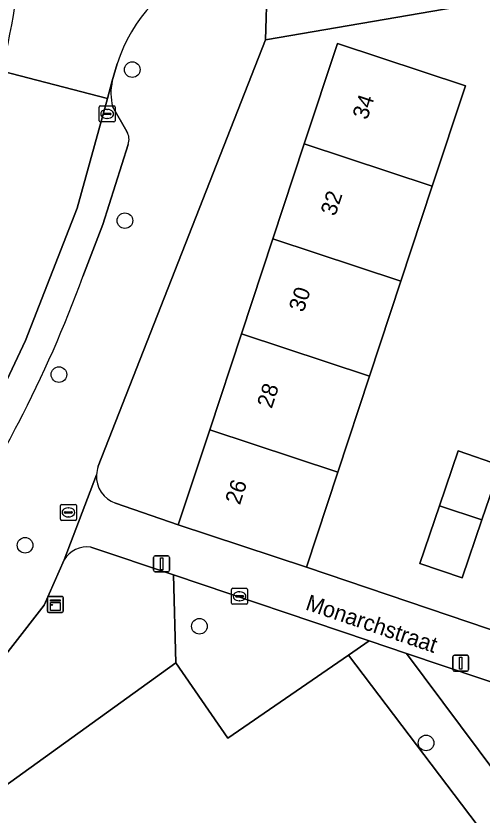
# Model space of a CAD drawing. Extents: x 162879 to 165540, y 384011 to 385181.
# Drawn here: x 164285.2 to 164314.4, y 384347 to 384397 of the extents above; entities that cross this region are included whole.
import ezdxf

# ---------------------------------------------------------------- set-up
doc = ezdxf.new("R2010")
doc.units = 0
for name, color, linetype in [('IMGEO_Boom', 7, 'Continuous'), ('IMGEO_Brandkraan', 7, 'Continuous'), ('IMGEO_Erf', 7, 'Continuous'), ('IMGEO_Groenvoorziening', 7, 'Continuous'), ('IMGEO_Kast', 7, 'Continuous'), ('IMGEO_Kolk', 7, 'Continuous'), ('IMGEO_Lichtmast', 7, 'Continuous'), ('IMGEO_Muur', 7, 'Continuous'), ('IMGEO_Openbare_ruimte_label', 7, 'Continuous'), ('IMGEO_Pand', 7, 'Continuous'), ('IMGEO_Pand_nummerreeks', 7, 'Continuous'), ('IMGEO_Parkeervlak_open', 7, 'Continuous'), ('IMGEO_Rijbaan_lokaal_gesloten', 7, 'Continuous'), ('IMGEO_Voetpad_open', 7, 'Continuous')]:
    doc.layers.add(name, color=color, linetype=linetype)

msp = doc.modelspace()

# ---------------------------------------------------------------- linework, layer by layer
at = {"layer": 'IMGEO_Boom'}
for centre in [(164292.513, 384393.64), (164292.05, 384384.2), (164287.921, 384374.581), (164285.802, 384363.909), (164296.713, 384358.845), (164310.898, 384351.552)]:
    msp.add_circle(centre, 0.489, dxfattribs=at)
at = {"layer": 'IMGEO_Brandkraan'}
for p, q in [((164288.091, 384366.466), (164288.943, 384366.466)), ((164288.016, 384365.54), (164288.016, 384366.392)), ((164288.275, 384365.96), (164288.275, 384365.972)), ((164288.713, 384365.923), (164288.315, 384365.923)), ((164288.318, 384366.009), (164288.716, 384366.009)), ((164288.504, 384366.246), (164288.529, 384366.246)), ((164288.759, 384365.972), (164288.759, 384365.96)), ((164289.017, 384366.392), (164289.017, 384365.54)), ((164288.943, 384365.466), (164288.091, 384365.466)), ((164288.527, 384365.686), (164288.502, 384365.686))]:
    msp.add_line(p, q, dxfattribs=at)
for points in [[(164288.091, 384366.466), (164288.943, 384366.466)], [(164288.016, 384365.54), (164288.016, 384366.392)], [(164289.017, 384366.392), (164289.017, 384365.54)], [(164288.943, 384365.466), (164288.091, 384365.466)]]:
    msp.add_lwpolyline(points, dxfattribs=at)
for centre, radius, start, end in [((164288.093, 384366.39), 0.0765, 91.552, 178.448), ((164288.093, 384366.39), 0.0765, 91.552, 178.448), ((164288.941, 384366.39), 0.0765, 1.552, 88.448), ((164288.941, 384366.39), 0.0765, 1.552, 88.448), ((164288.315, 384365.969), 0.0403, 85.8775, 175.7526), ((164288.312, 384365.959), 0.0366, 178.938, 274.7102), ((164288.716, 384365.966), 0.043, 264.8664, 352.4533), ((164288.72, 384365.971), 0.0386, 1.7309, 96.639), ((164288.093, 384365.542), 0.0765, 181.552, 268.448), ((164288.093, 384365.542), 0.0765, 181.552, 268.448), ((164288.941, 384365.542), 0.0765, 271.552, 358.448), ((164288.941, 384365.542), 0.0765, 271.552, 358.448)]:
    msp.add_arc(centre, radius, start, end, dxfattribs=at)
for centre, major_axis, ratio, start_param, end_param in [((164288.503, 384365.966), (-0.387, 0.002), 0.722429, 4.712389, 7.853982), ((164288.528, 384365.966), (-0.39, 0.002), 0.717154, 1.570796, 4.712389)]:
    msp.add_ellipse(centre, major_axis=major_axis, ratio=ratio, start_param=start_param, end_param=end_param, dxfattribs=at)
at = {"layer": 'IMGEO_Erf'}
for points in [[(164322.38, 384399.228), (164323.48, 384392.97), (164320.579, 384392.46), (164319.479, 384398.719), (164300.857, 384395.508), (164290.386, 384368.845)], [(164291.467, 384366.544), (164295.391, 384365.198), (164297.356, 384371.133), (164299.342, 384377.134), (164301.306, 384383.069), (164303.273, 384389.01), (164305.35, 384395.284), (164313.364, 384392.631), (164311.287, 384386.356), (164309.32, 384380.415), (164307.356, 384374.481), (164305.37, 384368.48), (164303.405, 384362.545), (164312.353, 384359.518), (164328.101, 384354.18), (164336.681, 384351.206), (164340.184, 384353.954), (164340.677, 384354.322), (164349.365, 384304.294)], [(164318.801, 384340.237), (164306.038, 384357.047), (164298.497, 384351.847), (164295.237, 384356.554), (164274.424, 384341.583)]]:
    msp.add_lwpolyline(points, dxfattribs=at)
msp.add_lwpolyline([(164313.159, 384361.874), (164310.513, 384362.779), (164311.741, 384366.371), (164312.916, 384369.805), (164315.562, 384368.9), (164314.396, 384365.492)], close=True, dxfattribs=at)
for centre, radius, start, end in [((164292.026, 384368.207), 1.76, 158.7414, 176.2474), ((164292.022, 384368.209), 1.755, 176.3241, 251.575)]:
    msp.add_arc(centre, radius, start, end, dxfattribs=at)
at = {"layer": 'IMGEO_Groenvoorziening'}
for points in [[(164295.237, 384356.554), (164295.092, 384362.062), (164289.927, 384363.801)], [(164288.245, 384362.997), (164286.999, 384360.158), (164281.086, 384352.605), (164272.712, 384342.789), (164274.424, 384341.583), (164295.237, 384356.554)]]:
    msp.add_lwpolyline(points, dxfattribs=at)
for points in [[(164295.092, 384362.062), (164295.237, 384356.554), (164298.497, 384351.847), (164306.038, 384357.047), (164307.335, 384357.942)], [(164309.676, 384357.153), (164307.335, 384357.942), (164306.038, 384357.047), (164318.801, 384340.237), (164318.942, 384340.051), (164325.389, 384345.149), (164326.82, 384346.216), (164327.179, 384345.735), (164328.028, 384348.252), (164320.302, 384342.936), (164318.706, 384345.071)], [(164321.331, 384353.226), (164309.676, 384357.153), (164318.706, 384345.071)]]:
    msp.add_lwpolyline(points, close=True, dxfattribs=at)
msp.add_arc((164289.71, 384362.094), 1.721, 82.7487, 148.3471, dxfattribs=at)
at = {"layer": 'IMGEO_Kast'}
for p, q in [((164287.197, 384359.79), (164287.197, 384360.631)), ((164287.197, 384360.631), (164287.197, 384359.79)), ((164287.272, 384360.715), (164288.113, 384360.715)), ((164288.113, 384360.715), (164287.272, 384360.715)), ((164288.197, 384360.64), (164288.197, 384359.799)), ((164288.197, 384359.799), (164288.197, 384360.64)), ((164288.122, 384359.715), (164287.281, 384359.715)), ((164287.281, 384359.715), (164288.122, 384359.715))]:
    msp.add_line(p, q, dxfattribs=at)
for points in [[(164287.392, 384360.505), (164287.992, 384360.505), (164287.992, 384360.42), (164287.392, 384360.42), (164287.392, 384360.505)], [(164287.392, 384360.33), (164287.992, 384360.33), (164287.992, 384359.841), (164287.392, 384359.841), (164287.392, 384360.33)]]:
    msp.add_lwpolyline(points, dxfattribs=at)
msp.add_circle((164287.476, 384360.179), 0.0377, dxfattribs=at)
for centre, start, end in [((164287.275, 384360.637), 92.4484, 184.2845), ((164287.275, 384360.637), 92.4484, 184.2845), ((164288.119, 384360.637), 2.4484, 94.2845), ((164288.119, 384360.637), 2.4484, 94.2845), ((164287.275, 384359.793), 182.4484, 274.2845), ((164287.275, 384359.793), 182.4484, 274.2845), ((164288.119, 384359.793), 272.4484, 4.2845), ((164288.119, 384359.793), 272.4484, 4.2845)]:
    msp.add_arc(centre, 0.0779, start, end, dxfattribs=at)
at = {"layer": 'IMGEO_Kolk'}
for p, q in [((164290.441, 384390.448), (164290.441, 384391.3)), ((164290.516, 384391.374), (164291.368, 384391.374)), ((164290.743, 384390.917), (164291.141, 384390.917)), ((164290.929, 384391.154), (164290.954, 384391.154)), ((164291.442, 384391.3), (164291.442, 384390.448)), ((164290.7, 384390.868), (164290.7, 384390.88)), ((164291.138, 384390.831), (164290.74, 384390.831)), ((164290.952, 384390.594), (164290.927, 384390.594)), ((164291.184, 384390.88), (164291.184, 384390.868)), ((164291.368, 384390.374), (164290.516, 384390.374)), ((164298.724, 384360.293), (164298.724, 384361.145)), ((164298.799, 384361.219), (164299.651, 384361.219)), ((164299.212, 384360.999), (164299.237, 384360.999)), ((164299.725, 384361.145), (164299.725, 384360.293)), ((164298.983, 384360.713), (164298.983, 384360.725)), ((164299.421, 384360.676), (164299.023, 384360.676)), ((164299.026, 384360.762), (164299.424, 384360.762)), ((164299.235, 384360.439), (164299.21, 384360.439)), ((164299.467, 384360.725), (164299.467, 384360.713)), ((164299.651, 384360.219), (164298.799, 384360.219))]:
    msp.add_line(p, q, dxfattribs=at)
for points in [[(164290.441, 384390.448), (164290.441, 384391.3)], [(164290.516, 384391.374), (164291.368, 384391.374)], [(164291.442, 384391.3), (164291.442, 384390.448)], [(164291.368, 384390.374), (164290.516, 384390.374)], [(164298.724, 384360.293), (164298.724, 384361.145)], [(164298.799, 384361.219), (164299.651, 384361.219)], [(164299.725, 384361.145), (164299.725, 384360.293)], [(164299.651, 384360.219), (164298.799, 384360.219)]]:
    msp.add_lwpolyline(points, dxfattribs=at)
for centre, radius, start, end in [((164290.518, 384391.298), 0.0765, 91.552, 178.448), ((164290.518, 384391.298), 0.0765, 91.552, 178.448), ((164290.74, 384390.877), 0.0403, 85.8775, 175.7526), ((164291.145, 384390.879), 0.0386, 1.7309, 96.639), ((164291.366, 384391.298), 0.0765, 1.552, 88.448), ((164291.366, 384391.298), 0.0765, 1.552, 88.448), ((164290.518, 384390.45), 0.0765, 181.552, 268.448), ((164290.518, 384390.45), 0.0765, 181.552, 268.448), ((164290.737, 384390.867), 0.0366, 178.938, 274.7102), ((164291.141, 384390.874), 0.043, 264.8664, 352.4533), ((164291.366, 384390.45), 0.0765, 271.552, 358.448), ((164291.366, 384390.45), 0.0765, 271.552, 358.448), ((164298.801, 384361.143), 0.0765, 91.552, 178.448), ((164298.801, 384361.143), 0.0765, 91.552, 178.448), ((164299.649, 384361.143), 0.0765, 1.552, 88.448), ((164299.649, 384361.143), 0.0765, 1.552, 88.448), ((164299.023, 384360.722), 0.0403, 85.8775, 175.7526), ((164299.02, 384360.712), 0.0366, 178.938, 274.7102), ((164299.424, 384360.719), 0.043, 264.8664, 352.4533), ((164299.428, 384360.724), 0.0386, 1.7309, 96.639), ((164298.801, 384360.295), 0.0765, 181.552, 268.448), ((164298.801, 384360.295), 0.0765, 181.552, 268.448), ((164299.649, 384360.295), 0.0765, 271.552, 358.448), ((164299.649, 384360.295), 0.0765, 271.552, 358.448)]:
    msp.add_arc(centre, radius, start, end, dxfattribs=at)
for centre, major_axis, ratio, start_param, end_param in [((164290.928, 384390.874), (-0.387, 0.002), 0.722429, 4.712389, 7.853982), ((164290.953, 384390.874), (-0.39, 0.002), 0.717154, 1.570796, 4.712389), ((164299.211, 384360.719), (-0.387, 0.002), 0.722429, 4.712389, 7.853982), ((164299.236, 384360.719), (-0.39, 0.002), 0.717154, 1.570796, 4.712389)]:
    msp.add_ellipse(centre, major_axis=major_axis, ratio=ratio, start_param=start_param, end_param=end_param, dxfattribs=at)
at = {"layer": 'IMGEO_Lichtmast'}
for p, q in [((164293.848, 384362.348), (164293.848, 384363.148)), ((164293.848, 384363.148), (164293.848, 384362.348)), ((164293.948, 384363.248), (164294.738, 384363.248)), ((164294.738, 384363.248), (164293.948, 384363.248)), ((164294.838, 384363.148), (164294.838, 384362.348)), ((164294.838, 384362.348), (164294.838, 384363.148)), ((164294.738, 384362.248), (164293.948, 384362.248)), ((164293.948, 384362.248), (164294.738, 384362.248)), ((164312.572, 384356.136), (164312.572, 384356.936)), ((164312.572, 384356.936), (164312.572, 384356.136)), ((164312.672, 384357.036), (164313.462, 384357.036)), ((164313.462, 384357.036), (164312.672, 384357.036)), ((164313.562, 384356.936), (164313.562, 384356.136)), ((164313.562, 384356.136), (164313.562, 384356.936)), ((164313.462, 384356.036), (164312.672, 384356.036)), ((164312.672, 384356.036), (164313.462, 384356.036))]:
    msp.add_line(p, q, dxfattribs=at)
for points in [[(164294.268, 384363.123), (164294.418, 384363.123), (164294.418, 384362.373), (164294.268, 384362.373), (164294.268, 384363.123)], [(164312.992, 384356.911), (164313.142, 384356.911), (164313.142, 384356.161), (164312.992, 384356.161), (164312.992, 384356.911)]]:
    msp.add_lwpolyline(points, dxfattribs=at)
for centre, start, end in [((164293.948, 384363.148), 90, 180), ((164293.948, 384363.148), 90, 180), ((164294.738, 384363.148), 0, 90), ((164294.738, 384363.148), 360, 90), ((164293.948, 384362.348), 180, 270), ((164293.948, 384362.348), 180, 270), ((164294.738, 384362.348), 270, 0), ((164294.738, 384362.348), 270, 0), ((164312.672, 384356.936), 90, 180), ((164312.672, 384356.936), 90, 180), ((164313.462, 384356.936), 0, 90), ((164313.462, 384356.936), 360, 90), ((164312.672, 384356.136), 180, 270), ((164312.672, 384356.136), 180, 270), ((164313.462, 384356.136), 270, 0), ((164313.462, 384356.136), 270, 0)]:
    msp.add_arc(centre, 0.1, start, end, dxfattribs=at)
at = {"layer": 'IMGEO_Muur'}
msp.add_lwpolyline([(164312.353, 384359.518), (164303.405, 384362.545)], dxfattribs=at)
at = {"layer": 'IMGEO_Pand'}
for points in [[(164311.287, 384386.356), (164313.364, 384392.631), (164305.35, 384395.284), (164303.273, 384389.01)], [(164311.287, 384386.356), (164303.273, 384389.01), (164301.306, 384383.069), (164309.32, 384380.415)], [(164307.356, 384374.481), (164309.32, 384380.415), (164301.306, 384383.069), (164299.342, 384377.134)], [(164307.356, 384374.481), (164299.342, 384377.134), (164297.356, 384371.133), (164305.37, 384368.48)], [(164305.37, 384368.48), (164297.356, 384371.133), (164295.391, 384365.198), (164303.405, 384362.545)], [(164311.741, 384366.371), (164314.396, 384365.492), (164315.562, 384368.9), (164312.916, 384369.805)], [(164311.741, 384366.371), (164310.513, 384362.779), (164313.159, 384361.874), (164314.396, 384365.492)]]:
    msp.add_lwpolyline(points, close=True, dxfattribs=at)
at = {"layer": 'IMGEO_Parkeervlak_open'}
for points in [[(164291.262, 384392.931), (164290.958, 384391.829), (164289.066, 384384.974), (164285.827, 384376.709), (164284.485, 384373.867), (164282.166, 384369.713)], [(164292.18, 384389.77), (164291.278, 384391.33)], [(164289.419, 384380.718), (164290.666, 384383.958), (164292.256, 384388.953)]]:
    msp.add_lwpolyline(points, dxfattribs=at)
for centre, radius, start, end in [((164214.239, 384409.661), 71.95, 347.05753, 2.13317), ((164294.595, 384392.164), 3.42, 167.0373, 194.1079), ((164291.278, 384389.274), 1.029, 341.816, 28.813), ((164216.919, 384407.167), 77.174, 332.52387, 339.95701), ((164198.31, 384416.62), 98.045, 325.60865, 332.64034)]:
    msp.add_arc(centre, radius, start, end, dxfattribs=at)
at = {"layer": 'IMGEO_Rijbaan_lokaal_gesloten'}
for points in [[(164284.361, 384393.546), (164290.958, 384391.829), (164291.262, 384392.931), (164291.575, 384393.997)], [(164282.166, 384369.713), (164284.485, 384373.867), (164285.827, 384376.709), (164289.066, 384384.974), (164290.958, 384391.829), (164284.361, 384393.546), (164284.346, 384393.48), (164284.331, 384393.415), (164282.225, 384387.049)]]:
    msp.add_lwpolyline(points, dxfattribs=at)
for centre, radius, start, end in [((164214.239, 384409.661), 71.95, 347.05753, 2.13317), ((164300.494, 384391.289), 9.321, 109.2809, 163.1103)]:
    msp.add_arc(centre, radius, start, end, dxfattribs=at)
at = {"layer": 'IMGEO_Voetpad_open'}
for points in [[(164300.944, 384398.99), (164300.857, 384395.508), (164319.479, 384398.719), (164322.38, 384399.228), (164330.155, 384400.608), (164332.974, 384401.104), (164345.117, 384403.27), (164347.887, 384403.757), (164355.475, 384405.078), (164358.523, 384405.613)], [(164300.857, 384395.508), (164300.944, 384398.99), (164299.301, 384400.126)], [(164290.386, 384368.845), (164300.857, 384395.508)], [(164291.575, 384393.997), (164291.262, 384392.931)], [(164291.278, 384391.33), (164292.18, 384389.77)], [(164292.256, 384388.953), (164290.666, 384383.958), (164289.419, 384380.718)], [(164239.208, 384301.296), (164239.944, 384299.935), (164241.621, 384301.03), (164241.784, 384302.243), (164244.454, 384315.55), (164245.34, 384316.175), (164245.639, 384315.799), (164251.674, 384320.699), (164260.84, 384329.156), (164268.366, 384337.124), (164268.257, 384337.301), (164274.424, 384341.583), (164272.712, 384342.789), (164281.086, 384352.605), (164286.999, 384360.158), (164288.245, 384362.997), (164290.27, 384368.322)], [(164290.27, 384368.322), (164288.245, 384362.997)], [(164349.365, 384304.294), (164340.677, 384354.322), (164340.184, 384353.954), (164336.681, 384351.206), (164328.101, 384354.18), (164312.353, 384359.518), (164303.405, 384362.545), (164295.391, 384365.198), (164291.467, 384366.544)], [(164289.927, 384363.801), (164295.092, 384362.062), (164307.335, 384357.942), (164309.676, 384357.153), (164321.331, 384353.226), (164326.135, 384351.608), (164328.865, 384350.737), (164328.028, 384348.252), (164327.179, 384345.735), (164327.439, 384345.929), (164328.827, 384345.442), (164330.426, 384350.194), (164336.418, 384348.146), (164334.723, 384343.375), (164335.647, 384343.051)]]:
    msp.add_lwpolyline(points, dxfattribs=at)
for centre, radius, start, end in [((164300.494, 384391.289), 9.321, 109.2809, 163.1103), ((164294.595, 384392.164), 3.42, 167.0373, 194.1079), ((164291.278, 384389.274), 1.029, 341.816, 28.813), ((164216.919, 384407.167), 77.174, 332.52387, 339.95701), ((164198.31, 384416.62), 98.045, 325.60865, 332.64034), ((164292.026, 384368.207), 1.76, 158.7414, 176.2474), ((164292.022, 384368.209), 1.755, 176.3241, 251.575), ((164289.71, 384362.094), 1.721, 82.7487, 148.3471)]:
    msp.add_arc(centre, radius, start, end, dxfattribs=at)

# ---------------------------------------------------------------- texts
at = {"layer": 'IMGEO_Openbare_ruimte_label'}
msp.add_text('Monarchstraat', height=1, rotation=341.3294, dxfattribs=at).set_placement((164303.291, 384359.907))
at = {"layer": 'IMGEO_Pand_nummerreeks'}
for s, p in [('34', (164307.209, 384390.46)), ('32', (164305.216, 384384.44)), ('30', (164303.226, 384378.429)), ('28', (164301.234, 384372.411)), ('26', (164299.242, 384366.391))]:
    msp.add_text(s, height=1, rotation=71.6845, dxfattribs=at).set_placement(p)

doc.saveas('drawing.dxf')
